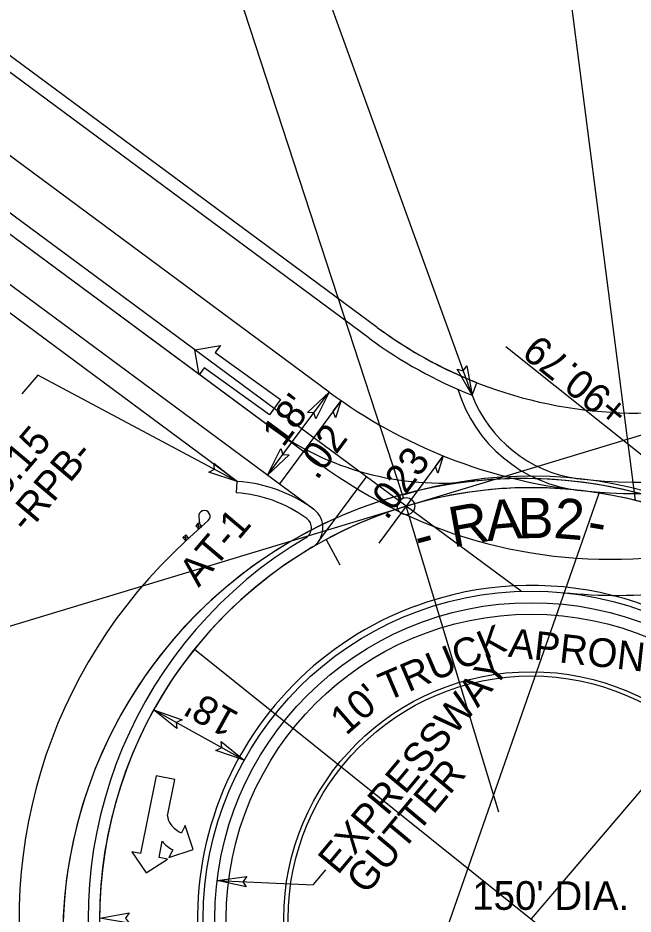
# Model space of a CAD drawing. Extents: x 1761082 to 1764358, y 421907 to 425434.
# Drawn here: x 1762617.9 to 1762724.8, y 423617.8 to 423773.7 of the extents above; entities that cross this region are included whole.
import ezdxf

# ---------------------------------------------------------------- set-up
doc = ezdxf.new("R2010")
doc.units = 0
for name, color, linetype in [('MARK HOOKS CENTER STRAIGHT LEFT TURN ARROW CELL', 7, 'Continuous'), ('MARK HOOKS STRAIGHT RIGHT TURN ARROW CELL', 7, 'Continuous'), ('MARK LEFT TURN ARROW CELL', 7, 'Continuous'), ('MARK STRAIGHT RIGHT ARROW CELL', 7, 'Continuous'), ('MARK UTURN ARROW CELL', 7, 'Continuous'), ('Prop Conc Shoulder Berm Gutter', 7, 'Continuous'), ('Prop Horizontal Alignment Tick Large', 7, 'Continuous'), ('Prop Mkg 3ft Min Skp 3ft Wide White', 7, 'Continuous'), ('Prop Mkg 3ft Min Skp 9ft White', 7, 'Continuous'), ('Prop Mkg 3ft Min Skp 9ft Wide White', 7, 'Continuous'), ('Prop Mkg Min Skp 6ft Yellow', 7, 'Continuous'), ('Prop Mkg Skp Wht', 7, 'Continuous'), ('Prop Mkg Solid White Diagonals', 7, 'Continuous'), ('Prop Mkg Solid White Edge Line', 7, 'Continuous'), ('Prop Mkg Solid White Gore Line', 7, 'Continuous'), ('Prop Mkg Solid White Multiple Diagonals V8i', 7, 'Continuous'), ('Prop Mkg Solid White Stop Bar', 7, 'Continuous'), ('Prop Mkg Solid White Wide Lane Line', 7, 'Continuous'), ('Prop Mkg Solid Yel Skip LT', 7, 'Continuous'), ('Prop Mkg Solid Yel Skip RT', 7, 'Continuous'), ('Prop Mkg Solid Yellow Diagonals', 7, 'Continuous'), ('Prop Mkg Solid Yellow Edge Line', 7, 'Continuous'), ('Prop Mkg Solid Yellow Lane Line', 7, 'Continuous'), ('Prop Mkg Yld Lin', 7, 'Continuous'), ('Prop Mkr Yel 80ft Spc', 7, 'Continuous'), ('Scratch_Level_0', 7, 'Continuous'), ('Scratch_Level_1', 7, 'Continuous'), ('Scratch_Level_5', 7, 'Continuous')]:
    doc.layers.add(name, color=color, linetype=linetype)

msp = doc.modelspace()

# ---------------------------------------------------------------- linework, layer by layer
at = {"layer": 'MARK HOOKS CENTER STRAIGHT LEFT TURN ARROW CELL'}
msp.add_line((1762671.42, 423682.96), (1762673.79, 423678.56), dxfattribs=at)
at = {"layer": 'MARK LEFT TURN ARROW CELL'}
msp.add_line((1762655.85, 423691.06), (1762655.98, 423693.06), dxfattribs=at)
for centre, radius, start, end in [((1762725.06, 423770.93), 78, 262.5595, 318.8196), ((1762718.24, 423716.35), 23, 201.1169, 261.8148), ((1762707.06, 423616.97), 77, 83.3316, 83.5849), ((1762654.38, 423668.11), 23, 53.4908, 86.3507), ((1762666.88, 423684.99), 2, 300.5769, 53.4908), ((1762707.06, 423616.97), 77, 120.5769, 194.1003)]:
    msp.add_arc(centre, radius, start, end, dxfattribs=at)
at = {"layer": 'MARK STRAIGHT RIGHT ARROW CELL'}
msp.add_line((1762685.32, 423688.75), (1762356.55, 423932.12), dxfattribs=at)
at = {"layer": 'MARK UTURN ARROW CELL'}
msp.add_lwpolyline([(1762684.86, 423690.18), (1762629.61, 423859.52), (1762714.68, 423959.94)], dxfattribs=at)
msp.add_circle((1762685.32, 423688.75), 1.5, dxfattribs=at)
msp.add_circle((1762685.32, 423688.75), 1.5, dxfattribs=at)
at = {"layer": 'Prop Conc Shoulder Berm Gutter'}
for p, q in [((1762680.28, 423719.85), (1762499.43, 423853.72)), ((1762696.78, 423708.06), (1762697.64, 423710.23))]:
    msp.add_line(p, q, dxfattribs=at)
msp.add_arc((1762725.5, 423780.94), 76, 233.4908, 248.4931, dxfattribs=at)
at = {"layer": 'Prop Horizontal Alignment Tick Large'}
msp.add_line((1762685.32, 423688.75), (1762680.56, 423682.32), dxfattribs=at)
at = {"layer": 'Prop Mkg 3ft Min Skp 3ft Wide White'}
msp.add_line((1762685.32, 423688.75), (1762356.55, 423932.12), dxfattribs=at)
for start, end in [(38.8816, 106.8512), (106.8512, 249.1952)]:
    msp.add_arc((1762707.06, 423616.97), 75, start, end, dxfattribs=at)
at = {"layer": 'Prop Mkg 3ft Min Skp 9ft White'}
msp.add_circle((1762707.06, 423616.97), 55, dxfattribs=at)
at = {"layer": 'Prop Mkg 3ft Min Skp 9ft Wide White'}
msp.add_line((1762680.28, 423719.85), (1762502.5, 423851.46), dxfattribs=at)
for centre, radius, start, end in [((1762725.5, 423780.94), 76, 233.4908, 271.2744), ((1762707.06, 423616.97), 89, 132.3949, 194.1003)]:
    msp.add_arc(centre, radius, start, end, dxfattribs=at)
at = {"layer": 'Prop Mkg Skp Wht'}
for p, q in [((1762671.95, 423708.6), (1762368.58, 423933.16)), ((1762669.26, 423688.2), (1762398.06, 423888.95))]:
    msp.add_line(p, q, dxfattribs=at)
for centre, radius, start, end in [((1762725.06, 423770.93), 80, 263.3316, 318.8196), ((1762725.5, 423780.94), 90, 233.4908, 263.5849), ((1762707.06, 423616.97), 75, 83.3316, 83.5849), ((1762666.88, 423684.99), 4, 300.5769, 53.4908), ((1762707.06, 423616.97), 75, 120.5769, 194.1003)]:
    msp.add_arc(centre, radius, start, end, dxfattribs=at)
at = {"layer": 'Prop Mkg Solid White Diagonals'}
for radius in [53, 43]:
    msp.add_circle((1762707.06, 423616.97), radius, dxfattribs=at)
at = {"layer": 'Prop Mkg Solid White Edge Line'}
for radius, start, end in [(77, 38.8816, 106.8512), (75, 38.8816, 106.8512), (75, 106.8512, 249.1952)]:
    msp.add_arc((1762707.06, 423616.97), radius, start, end, dxfattribs=at)
at = {"layer": 'Prop Mkg Solid White Gore Line'}
for radius in [43, 42.25]:
    msp.add_circle((1762707.06, 423616.97), radius, dxfattribs=at)
at = {"layer": 'Prop Mkg Solid White Multiple Diagonals V8i'}
for p, q in [((1762474.81, 423624.99), (1762733.71, 423703.41)), ((1762705.33, 423673.95), (1762685.32, 423688.75)), ((1762701.44, 423635.54), (1762685.32, 423688.75))]:
    msp.add_line(p, q, dxfattribs=at)
for radius in [57, 53]:
    msp.add_circle((1762707.06, 423616.97), radius, dxfattribs=at)
for centre, radius, start, end in [((1762707.06, 423616.97), 75, 83.5849, 117.8454), ((1762722.27, 423773.24), 100, 264.4409, 286.8732), ((1762707.06, 423616.97), 58, 332.6013, 110.42), ((1762707.06, 423616.97), 58, 110.3706, 210.5769)]:
    msp.add_arc(centre, radius, start, end, dxfattribs=at)
at = {"layer": 'Prop Mkg Solid White Stop Bar'}
for p, q in [((1762655.98, 423693.06), (1762395.68, 423885.73)), ((1762678.9, 423717.98), (1762498.05, 423851.85))]:
    msp.add_line(p, q, dxfattribs=at)
for centre, radius, start, end in [((1762725.5, 423780.94), 78.33, 233.4908, 248.4931), ((1762718.24, 423716.35), 25, 196.8961, 263.5849), ((1762654.38, 423668.11), 25, 53.4908, 86.3507)]:
    msp.add_arc(centre, radius, start, end, dxfattribs=at)
at = {"layer": 'Prop Mkg Solid White Wide Lane Line'}
for p, q in [((1762670.22, 423551.65), (1762718.86, 423691.04)), ((1762755.65, 423674.11), (1762707.06, 423616.97)), ((1762648.54, 423663.87), (1762765.59, 423570.08))]:
    msp.add_line(p, q, dxfattribs=at)
msp.add_arc((1762705.65, 423613.56), 80, 12.8164, 194.1392, dxfattribs=at)
at = {"layer": 'Prop Mkg Solid Yel Skip RT'}
for p, q in [((1762702.64, 423716.55), (1762732.44, 423692.71)), ((1762661.25, 423694.13), (1762671.95, 423708.6)), ((1762657.2, 423644.59), (1762641.45, 423653.31))]:
    msp.add_line(p, q, dxfattribs=at)
for points in [[(1762696.78, 423708.06), (1762664.07, 423798.6), (1762695, 423835.12)], [(1762655.98, 423693.06), (1762621.32, 423711.56), (1762618.55, 423708.3)], [(1762652.47, 423623.65), (1762669.15, 423622.91), (1762671.36, 423625.52)]]:
    msp.add_lwpolyline(points, dxfattribs=at)
at = {"layer": 'Prop Mkg Solid Yellow Diagonals'}
for p, q in [((1762648.61, 423715.95), (1762653.04, 423716.7)), ((1762653.04, 423716.7), (1762652.16, 423715.48)), ((1762649.35, 423711.59), (1762648.61, 423715.95)), ((1762652.16, 423715.48), (1762663.51, 423707.29)), ((1762650.23, 423712.81), (1762649.35, 423711.59)), ((1762661.58, 423704.61), (1762650.23, 423712.81)), ((1762663.51, 423707.29), (1762661.58, 423704.61)), ((1762641.9, 423641.86), (1762639.15, 423628.34)), ((1762645.13, 423641.2), (1762641.9, 423641.86)), ((1762643.85, 423634.88), (1762645.13, 423641.2)), ((1762646.93, 423633.24), (1762646.26, 423631.94)), ((1762648.32, 423629.03), (1762646.93, 423633.24)), ((1762642.39, 423627.68), (1762642.95, 423630.47)), ((1762644.11, 423627.64), (1762648.32, 423629.03)), ((1762639.15, 423628.34), (1762637.68, 423628.63)), ((1762637.68, 423628.63), (1762640.15, 423624.97)), ((1762643.86, 423627.38), (1762642.39, 423627.68)), ((1762644.79, 423628.98), (1762644.11, 423627.64)), ((1762640.15, 423624.97), (1762643.86, 423627.38))]:
    msp.add_line(p, q, dxfattribs=at)
for centre, radius, start, end in [((1762646.37, 423635.02), 2.52, 183.1445, 219.4565), ((1762648.01, 423636.02), 4.43, 215.9664, 246.8199), ((1762646.54, 423633.07), 4.43, 216.0602, 246.9387)]:
    msp.add_arc(centre, radius, start, end, dxfattribs=at)
at = {"layer": 'Prop Mkg Solid Yellow Edge Line'}
msp.add_arc((1762707.06, 423616.97), 75, 53.8578, 83.3316, dxfattribs=at)
at = {"layer": 'Prop Mkg Solid Yellow Lane Line'}
for points in [[(1762695.87, 423713.16), (1762696.78, 423708.06), (1762694.19, 423712.58), (1762695.26, 423712.27)], [(1762668.21, 423705.02), (1762671.95, 423708.6), (1762669.63, 423703.94), (1762669.29, 423705)], [(1762664.99, 423697.71), (1762661.25, 423694.13), (1762663.57, 423698.8), (1762663.91, 423697.73)], [(1762651.89, 423696.24), (1762655.98, 423693.06), (1762651.02, 423694.68), (1762652.02, 423695.17)], [(1762645.49, 423650.06), (1762641.45, 423653.31), (1762646.38, 423651.61), (1762645.37, 423651.14)], [(1762653.16, 423647.83), (1762657.2, 423644.59), (1762652.27, 423646.28), (1762653.28, 423646.76)], [(1762657.53, 423622.55), (1762652.47, 423623.65), (1762657.64, 423624.33), (1762656.95, 423623.45)], [(1762637.17, 423616.22), (1762632.07, 423617.11), (1762637.2, 423618.01), (1762636.54, 423617.1)]]:
    msp.add_lwpolyline(points, close=True, dxfattribs=at)
at = {"layer": 'Prop Mkg Yld Lin'}
for p, q in [((1762649.28, 423686.89), (1762649.4, 423685.69)), ((1762647.06, 423682.7), (1762649.67, 423685.1)), ((1762649.27, 423685.83), (1762648.76, 423685.35)), ((1762648.76, 423685.35), (1762649.3, 423684.76)), ((1762649.82, 423685.23), (1762648.76, 423685.35)), ((1762649.82, 423685.23), (1762649.27, 423685.83)), ((1762649.3, 423684.76), (1762649.27, 423685.83)), ((1762649.3, 423684.76), (1762649.82, 423685.23)), ((1762649.82, 423685.23), (1762649.58, 423685.49)), ((1762649.82, 423685.23), (1762649.58, 423685.49)), ((1762649.72, 423685.14), (1762649.62, 423685.05)), ((1762649.72, 423685.14), (1762649.62, 423685.05)), ((1762649.67, 423685.1), (1762650.94, 423686.26)), ((1762647.03, 423683.77), (1762646.51, 423683.3)), ((1762647.57, 423683.17), (1762647.03, 423683.77)), ((1762647.06, 423682.7), (1762647.03, 423683.77)), ((1762646.51, 423683.3), (1762647.06, 423682.7)), ((1762647.57, 423683.17), (1762646.51, 423683.3)), ((1762647.06, 423682.7), (1762647.57, 423683.17))]:
    msp.add_line(p, q, dxfattribs=at)
msp.add_ellipse((1762650.27, 423686.99), major_axis=(-0.671, 0.732), ratio=0.995379, start_param=3.141593, end_param=7.214552, dxfattribs=at)
at = {"layer": 'Prop Mkr Yel 80ft Spc'}
msp.add_line((1762661.6, 423702.58), (1762566.59, 423772.91), dxfattribs=at)
for centre in [(1762661.6, 423702.58), (1762661.6, 423702.58), (1762696.85, 423693.07), (1762696.85, 423693.07)]:
    msp.add_circle(centre, 0.0417, dxfattribs=at)
for centre, radius, start, end in [((1762691.35, 423742.77), 50, 233.4908, 276.3138), ((1762705.65, 423613.56), 80, 41.9526, 96.3138)]:
    msp.add_arc(centre, radius, start, end, dxfattribs=at)
at = {"layer": 'Scratch_Level_0'}
msp.add_line((1762670.09, 423682.61), (1762678.42, 423693.86), dxfattribs=at)
at = {"layer": 'Scratch_Level_1'}
msp.add_line((1762670.21, 423696.21), (1762566.59, 423772.91), dxfattribs=at)
msp.add_lwpolyline([(1762725.19, 423689.75), (1762700.56, 423881.1), (1762754, 423944.18)], dxfattribs=at)
msp.add_circle((1762670.21, 423696.21), 0.0417, dxfattribs=at)
msp.add_circle((1762670.21, 423696.21), 0.0417, dxfattribs=at)
for centre, radius, start, end in [((1762720.78, 423764.53), 85, 233.4908, 319.7301), ((1762705.65, 423613.56), 80, 41.9526, 194.1392)]:
    msp.add_arc(centre, radius, start, end, dxfattribs=at)
at = {"layer": 'Scratch_Level_5'}
for p, q in [((1762674.03, 423707.11), (1762663.3, 423692.61)), ((1762691.79, 423697.49), (1762685.32, 423688.75))]:
    msp.add_line(p, q, dxfattribs=at)
for points in [[(1762674.03, 423707.11), (1762673.05, 423704.11), (1762672.65, 423705.25)], [(1762691.79, 423697.49), (1762690.81, 423694.49), (1762690.42, 423695.63)]]:
    msp.add_lwpolyline(points, close=True, dxfattribs=at)

# ---------------------------------------------------------------- texts
at = {"layer": 'MARK HOOKS STRAIGHT RIGHT TURN ARROW CELL'}
for s, rotation, p in [('A', 5.0178, (1762699.45, 423682.66)), ('B', 0.5547, (1762704.73, 423683.17)), ('2', 355.4173, (1762710.83, 423683.25)), ('R', 10.1552, (1762693.45, 423681.56)), ('-', 350.6174, (1762716.51, 423682.84)), ('-', 15.2064, (1762687.66, 423679.96))]:
    msp.add_text(s, height=7, rotation=rotation, dxfattribs=at).set_placement(p)
at = {"layer": 'Prop Mkg Min Skp 6ft Yellow'}
for s, p in [('.02', (1762669.84, 423693.13)), ('.023', (1762681.95, 423686.16))]:
    msp.add_text(s, height=5, rotation=53.4908, dxfattribs=at).set_placement(p)
at = {"layer": 'Prop Mkg Solid Yel Skip LT'}
for s, rotation, p in [("18'", 53.4908, (1762663.95, 423698.83)), ('+26.15', 49.7301, (1762610.55, 423684.23)), ('-RPB-', 49.7301, (1762619.43, 423683.88)), ('TRUCK', 23.0012, (1762681.93, 423654.76)), ('APRON', 353.674, (1762702.94, 423662.59)), ('EXPRESSWAY', 50.1302, (1762673.46, 423624.48)), ("10'", 41.0263, (1762674.89, 423648.76)), ("18'", 151.0256, (1762656.54, 423652.67)), ('GUTTER', 50.1302, (1762678.37, 423621.02)), ("150' DIA.", 359.8948, (1762696.8, 423618.56))]:
    msp.add_text(s, height=5, rotation=rotation, dxfattribs=at).set_placement(p)
at = {"layer": 'Prop Mkg Solid Yel Skip RT'}
msp.add_text('+90.79', height=5, rotation=141.3483, dxfattribs=at).set_placement((1762724.45, 423705.95))
at = {"layer": 'Prop Mkg Yld Lin'}
msp.add_text('AT-1', height=5, rotation=49.7301, dxfattribs=at).set_placement((1762649.27, 423674.51))

doc.saveas('drawing.dxf')
